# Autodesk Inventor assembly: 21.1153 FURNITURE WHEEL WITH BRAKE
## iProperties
Created: 2007-04
Part Number: 21.1153 FURNITURE WHEEL WITH BRAKE
Document SubType Name: Assembly
Designer: Andy Moles
Author: Andy Moles
